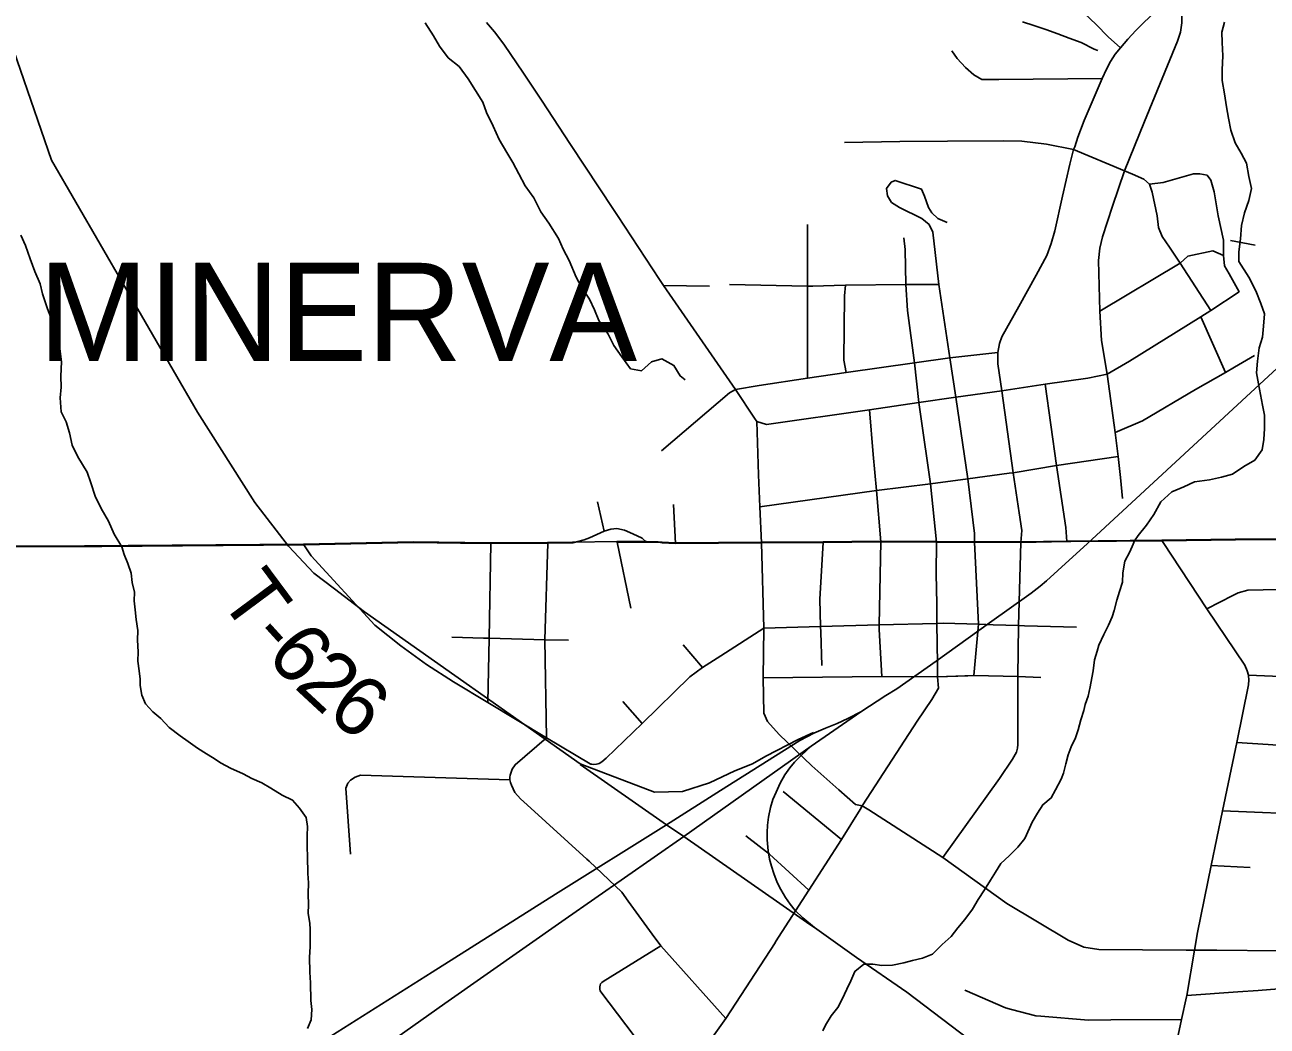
# Model space of a CAD drawing. Extents: x 0 to 34, y 0 to 22.
# Drawn here: x 4.481 to 5.679, y 16.545 to 17.511 of the extents above; entities that cross this region are included whole.
import ezdxf

# ---------------------------------------------------------------- set-up
doc = ezdxf.new("R2010")
doc.units = 0
for name, color, linetype in [('Default', 7, 'Continuous'), ('SH_Cut_Line', 7, 'Continuous'), ('SH_Data', 7, 'Continuous')]:
    doc.layers.add(name, color=color, linetype=linetype)

msp = doc.modelspace()

# ---------------------------------------------------------------- linework, layer by layer
at = {"layer": 'Default'}
for p, q in [((5.6519, 17.2539), (5.6423, 17.2712)), ((5.0967, 17.2599), (5.1412, 17.2591)), ((5.2408, 17.2592), (5.2612, 17.2598)), ((5.6388, 17.1759), (5.615, 17.2298)), ((5.6475, 17.181), (5.6667, 17.1924)), ((5.5396, 17.0545), (5.5375, 17.0747)), ((5.0396, 17.023), (5.033, 17.0511)), ((5.1082, 17.0111), (5.1063, 17.0485)), ((4.5548, 17.0081), (4.7497, 17.0097)), ((5.0652, 16.9486), (5.0519, 17.0123)), ((5.5778, 17.0136), (5.4898, 17.0128)), ((5.5789, 17.012), (5.5778, 17.0136)), ((5.1345, 16.8913), (5.1156, 16.9133)), ((5.3612, 16.8823), (5.3961, 16.8836)), ((5.3612, 16.8823), (5.3903, 16.8834)), ((5.3961, 16.8836), (5.4386, 16.8827)), ((5.4386, 16.8827), (5.4606, 16.8818)), ((5.076, 16.8373), (5.0576, 16.8587)), ((5.2684, 16.7254), (5.2122, 16.7717)), ((5.6252, 16.7002), (5.6628, 16.6984)), ((5.1077, 16.4842), (5.157, 16.5526))]:
    msp.add_line(p, q, dxfattribs=at)
for points in [[(4.7351, 17.0083), (4.7024, 17.0505), (4.6473, 17.1377), (4.5064, 17.3807), (4.4361, 17.5838), (4.404, 17.6885), (4.3215, 17.9209), (4.3028, 17.9921), (4.3143, 18.0833), (4.3281, 18.2195), (4.3343, 18.2932), (4.3327, 18.3689), (4.327, 18.4219)], [(5.5058, 17.0111), (5.7483, 17.2351), (5.9021, 17.375), (6.092, 17.5491), (6.2778, 17.7191)], [(5.3944, 17.5763), (5.4338, 17.5575), (5.4612, 17.546), (5.4969, 17.5281), (5.5142, 17.5118), (5.5257, 17.4999), (5.5375, 17.4893)], [(5.4934, 17.3938), (5.4965, 17.4031), (5.5026, 17.4191), (5.5133, 17.444), (5.5199, 17.4596), (5.524, 17.4686), (5.5279, 17.4759), (5.5324, 17.483), (5.5375, 17.4893), (5.5447, 17.4975), (5.5525, 17.506), (5.5932, 17.5464)], [(5.5314, 17.125), (5.5247, 17.1743), (5.5194, 17.2068), (5.5177, 17.235), (5.5163, 17.284), (5.5175, 17.296), (5.5203, 17.3069), (5.5299, 17.3364), (5.5414, 17.3705), (5.5608, 17.418), (5.5925, 17.4956), (5.5954, 17.5043), (5.5969, 17.5132), (5.5968, 17.5221), (5.5959, 17.532), (5.5932, 17.5464)], [(4.8669, 17.5133), (4.8747, 17.5009), (4.8805, 17.4907), (4.889, 17.4797), (4.8997, 17.4711), (4.9082, 17.4594), (4.9152, 17.4481), (4.9225, 17.4367), (4.9261, 17.4269), (4.9323, 17.4137), (4.9381, 17.4008), (4.9455, 17.3883), (4.9513, 17.3785), (4.9571, 17.3675), (4.9633, 17.3562), (4.9715, 17.3445), (4.9784, 17.3309), (4.9862, 17.3199), (4.9955, 17.3052), (4.9998, 17.295), (5.0056, 17.284), (5.0126, 17.2681), (5.0176, 17.2583), (5.0254, 17.2466), (5.0301, 17.2364), (5.0343, 17.2262), (5.0432, 17.213), (5.0487, 17.202), (5.0564, 17.1911), (5.0649, 17.1794), (5.0756, 17.1776), (5.0853, 17.1864), (5.0952, 17.1891), (5.1067, 17.1828), (5.1129, 17.1726), (5.1175, 17.1688)], [(4.9259, 17.5137), (4.9336, 17.5047), (4.9427, 17.4928), (4.9616, 17.4647), (4.9789, 17.4387), (5.0069, 17.396), (5.0484, 17.3332)], [(5.4432, 17.5142), (5.4539, 17.5108), (5.4657, 17.5068), (5.4771, 17.5027), (5.4882, 17.4986), (5.4996, 17.4942), (5.5123, 17.4878), (5.5157, 17.4867)], [(5.6378, 17.5141), (5.6352, 17.5042), (5.6357, 17.4943), (5.6363, 17.4814), (5.6356, 17.4681), (5.6358, 17.4578), (5.6378, 17.4449), (5.6398, 17.4324), (5.6419, 17.4214), (5.6439, 17.4097), (5.6482, 17.3975), (5.654, 17.3877), (5.6591, 17.3779), (5.6615, 17.365), (5.6639, 17.3536), (5.6614, 17.3418), (5.6573, 17.33), (5.6544, 17.3178), (5.6534, 17.3049), (5.6517, 17.2923), (5.6518, 17.2829), (5.6614, 17.2681), (5.668, 17.2549), (5.6731, 17.2424), (5.6766, 17.2326), (5.6756, 17.2208), (5.6746, 17.2101), (5.6713, 17.1998), (5.6699, 17.1869), (5.6689, 17.1755), (5.6706, 17.1649), (5.6746, 17.1444), (5.6766, 17.1349), (5.6764, 17.122), (5.6757, 17.1114), (5.6743, 17.1015), (5.6672, 17.0915), (5.6566, 17.0853), (5.6457, 17.078), (5.6351, 17.0749), (5.6233, 17.0725), (5.6089, 17.0705), (5.5987, 17.0658), (5.587, 17.0608), (5.5764, 17.0512), (5.5697, 17.0389), (5.5626, 17.0286), (5.5547, 17.0187), (5.5512, 17.0135)], [(5.375, 17.4864), (5.3799, 17.4788), (5.3879, 17.4703), (5.3961, 17.4631), (5.4037, 17.4588), (5.4159, 17.4587)], [(5.4159, 17.4587), (5.4203, 17.4587), (5.5199, 17.4596)], [(5.2712, 17.3978), (5.3246, 17.3988), (5.3706, 17.3992), (5.4249, 17.3996), (5.4424, 17.399), (5.4663, 17.3962), (5.4924, 17.391)], [(5.4231, 17.1584), (5.4194, 17.1842), (5.4192, 17.1951), (5.4207, 17.2041), (5.423, 17.2103), (5.4396, 17.2397), (5.4562, 17.2699), (5.4666, 17.2888), (5.4708, 17.3003), (5.4741, 17.3126), (5.4816, 17.3461), (5.4887, 17.3771), (5.4924, 17.391), (5.4934, 17.3938)], [(5.4924, 17.391), (5.5414, 17.3705), (5.5492, 17.3673), (5.5602, 17.3624), (5.5654, 17.3577), (5.5789, 17.3594), (5.6079, 17.3676), (5.614, 17.3677), (5.6212, 17.3664)], [(5.6423, 17.2712), (5.638, 17.279), (5.6371, 17.2888), (5.6368, 17.3035), (5.6317, 17.3272), (5.628, 17.3504), (5.6248, 17.3615), (5.6212, 17.3664)], [(5.3966, 17.0122), (5.3967, 17.0206), (5.3904, 17.0734), (5.3787, 17.1522), (5.3729, 17.19), (5.3623, 17.2609), (5.3564, 17.3115), (5.353, 17.3188), (5.3459, 17.3245), (5.3243, 17.3353), (5.3168, 17.34), (5.3127, 17.3464), (5.3118, 17.3535), (5.3164, 17.3597), (5.3202, 17.3613), (5.3457, 17.353), (5.3485, 17.346), (5.3523, 17.3353), (5.3557, 17.3299), (5.3613, 17.3245), (5.3704, 17.3206)], [(5.5654, 17.3577), (5.5681, 17.35), (5.573, 17.3272), (5.5741, 17.3158), (5.5777, 17.3072), (5.5849, 17.297), (5.5953, 17.2816), (5.6248, 17.2358)], [(5.0484, 17.3332), (5.0524, 17.3273), (5.0928, 17.2658)], [(5.2356, 17.1705), (5.2357, 17.2591), (5.2356, 17.3186)], [(4.4766, 17.3083), (4.4812, 17.2985), (4.4856, 17.2856), (4.4903, 17.2735), (4.4953, 17.2614), (4.4977, 17.2519), (4.5025, 17.2375), (4.5072, 17.2247), (4.5123, 17.2103), (4.5147, 17.1966), (4.5159, 17.1864), (4.5153, 17.1723), (4.5155, 17.1617), (4.5148, 17.1514), (4.5157, 17.1381)], [(5.3447, 17.1357), (5.3431, 17.147), (5.3387, 17.1852), (5.3321, 17.2357), (5.3306, 17.2609), (5.33, 17.2946), (5.3285, 17.3059)], [(5.5177, 17.235), (5.5953, 17.2816), (5.6024, 17.2881), (5.6268, 17.2935), (5.6371, 17.2888)], [(5.0928, 17.2658), (5.0967, 17.2599), (5.1661, 17.1595), (5.1845, 17.132)], [(5.1604, 17.261), (5.2357, 17.2591), (5.2408, 17.2592)], [(5.2612, 17.2598), (5.2724, 17.2601), (5.3306, 17.2609), (5.3623, 17.2609)], [(5.2728, 17.1759), (5.2708, 17.1879), (5.2713, 17.25), (5.2724, 17.2601)], [(5.4231, 17.1584), (5.4649, 17.1648), (5.506, 17.1704), (5.5247, 17.1743), (5.5462, 17.187), (5.615, 17.2298), (5.6248, 17.2358), (5.6519, 17.2539), (5.6519, 17.2539)], [(5.4231, 17.1584), (5.4649, 17.1648), (5.506, 17.1704), (5.5247, 17.1743), (5.5462, 17.187), (5.615, 17.2298), (5.6248, 17.2358), (5.6519, 17.2539), (5.6519, 17.2539)], [(5.0947, 17.1003), (5.1604, 17.1562), (5.1661, 17.1595), (5.1891, 17.1634), (5.2356, 17.1705), (5.2728, 17.1759), (5.3387, 17.1852), (5.3729, 17.19), (5.4192, 17.1951)], [(5.5323, 17.118), (5.5588, 17.1294), (5.61, 17.1594), (5.6388, 17.1759), (5.6475, 17.181)], [(5.4858, 17.0128), (5.4849, 17.0263), (5.476, 17.0863), (5.4649, 17.1648)], [(5.1845, 17.132), (5.1867, 17.1286), (5.1962, 17.1258), (5.2956, 17.1401), (5.3431, 17.147), (5.3787, 17.1522), (5.4231, 17.1584)], [(5.4414, 17.012), (5.4424, 17.0234), (5.4398, 17.0406), (5.4341, 17.0793), (5.4231, 17.1584)], [(4.5157, 17.1381), (4.5204, 17.1283), (4.5236, 17.1177), (4.5263, 17.1059), (4.5318, 17.0946), (4.5407, 17.0799), (4.5442, 17.0696), (4.5486, 17.0568), (4.5544, 17.0447), (4.5614, 17.0326), (4.5668, 17.0201), (4.5742, 17.0078)], [(5.3063, 17.0126), (5.3022, 17.0622), (5.2991, 17.097), (5.2956, 17.1401)], [(5.1914, 17.0116), (5.1897, 17.0462), (5.1884, 17.0771), (5.1867, 17.1286)], [(5.3601, 17.0124), (5.3543, 17.0685), (5.3447, 17.1357)], [(5.5375, 17.0747), (5.5353, 17.0949), (5.5323, 17.118), (5.5314, 17.125)], [(5.4302, 17.0788), (5.4341, 17.0793), (5.476, 17.0863), (5.5353, 17.0949)], [(5.1897, 17.0462), (5.3022, 17.0622), (5.3543, 17.0685), (5.3904, 17.0734), (5.4302, 17.0788)], [(4.9852, 17.0112), (5.0091, 17.0116), (5.0201, 17.0144), (5.0252, 17.0166), (5.0359, 17.0214), (5.0396, 17.023), (5.046, 17.0249), (5.0518, 17.0254), (5.059, 17.0238), (5.0672, 17.0204), (5.076, 17.016), (5.0804, 17.0122)], [(4.1345, 17.0111), (4.1998, 17.0105), (4.215, 17.011), (4.2236, 17.0113), (4.2347, 17.011), (4.2466, 17.0105), (4.2609, 17.0094), (4.2768, 17.0085), (4.3013, 17.0085), (4.3321, 17.0082), (4.4053, 17.008), (4.5384, 17.008), (4.5548, 17.0081)], [(4.4051, 17.0085), (4.5382, 17.0086), (4.7495, 17.0102), (4.8553, 17.0125), (4.9299, 17.0116), (4.9849, 17.0118), (5.0089, 17.0122), (5.0517, 17.0129), (5.0802, 17.0128), (5.0916, 17.0127), (5.0953, 17.0122), (5.1079, 17.0116), (5.1912, 17.0122), (5.2507, 17.0126), (5.3061, 17.0131), (5.3599, 17.0129), (5.3964, 17.0127), (5.4412, 17.0125), (5.4856, 17.0133), (5.5776, 17.0142), (5.6482, 17.0151), (5.706, 17.0155)], [(5.706, 17.0155), (5.6482, 17.0151), (5.5776, 17.0142), (5.4856, 17.0133), (5.4412, 17.0125), (5.3964, 17.0127), (5.3599, 17.0129), (5.3061, 17.0131), (5.2507, 17.0126), (5.1912, 17.0122), (5.1079, 17.0116), (5.0953, 17.0122), (5.0916, 17.0127), (5.0802, 17.0128), (5.0517, 17.0129), (5.0089, 17.0122), (4.9849, 17.0118), (4.9299, 17.0116), (4.8553, 17.0125), (4.7495, 17.0102), (4.5382, 17.0086), (4.4051, 17.0085)], [(4.5799, 16.9917), (4.5764, 17.0003), (4.5742, 17.0078)], [(5.0162, 16.7985), (4.8082, 16.9451), (4.7792, 16.9674), (4.7595, 16.9822), (4.7351, 17.0083)], [(4.7497, 17.0097), (4.8555, 17.0119), (4.9008, 17.0114)], [(4.7497, 17.0097), (4.7569, 16.999), (4.8181, 16.9321), (4.8432, 16.9124), (4.8682, 16.8941), (4.8942, 16.8774)], [(4.9008, 17.0114), (4.9301, 17.0111), (4.9852, 17.0112)], [(4.9273, 16.8575), (4.9287, 16.9197), (4.9301, 17.0111)], [(4.9838, 16.8236), (4.9822, 16.9182), (4.9852, 17.0112)], [(5.0519, 17.0123), (5.0804, 17.0122), (5.0918, 17.0122), (5.0955, 17.0116), (5.1082, 17.0111), (5.1914, 17.0116), (5.2509, 17.0121), (5.3063, 17.0126), (5.3601, 17.0124), (5.3966, 17.0122), (5.4414, 17.012)], [(5.6893, 16.6181), (5.6304, 16.6185), (5.609, 16.6187), (5.601, 16.6187), (5.5167, 16.6194), (5.5022, 16.6215), (5.487, 16.6282), (5.428, 16.6637), (5.3663, 16.708), (5.2947, 16.754), (5.2884, 16.7578), (5.2819, 16.7593), (5.2659, 16.7732), (5.2398, 16.7964), (5.2082, 16.8267), (5.1969, 16.8391), (5.1934, 16.8474), (5.1929, 16.8814), (5.1934, 16.9293), (5.1914, 17.0116)], [(5.2424, 16.6404), (5.2312, 16.6497), (5.2236, 16.657), (5.219, 16.663), (5.2145, 16.6693), (5.2099, 16.6771), (5.2063, 16.684), (5.203, 16.6925), (5.2008, 16.6996), (5.1991, 16.7065), (5.1978, 16.7144), (5.1968, 16.725), (5.1967, 16.7323), (5.1971, 16.7392), (5.1981, 16.7469), (5.2001, 16.7563), (5.2022, 16.7639), (5.2054, 16.7711), (5.2093, 16.7798), (5.2137, 16.7877), (5.2187, 16.7947), (5.2231, 16.8001), (5.2299, 16.8067), (5.2393, 16.8153), (5.287, 16.8487), (5.3113, 16.8642), (5.3219, 16.8709), (5.3597, 16.8976), (5.4113, 16.9344), (5.4513, 16.9631), (5.46, 16.9698), (5.4663, 16.975), (5.4772, 16.9848), (5.5058, 17.0111)], [(5.2494, 16.8933), (5.2484, 16.9253), (5.2483, 16.9308), (5.2475, 16.9572), (5.2509, 17.0121)], [(5.3073, 16.8827), (5.3049, 16.9279), (5.3048, 16.9324), (5.3063, 17.0126)], [(5.3612, 16.8823), (5.3609, 16.8948), (5.3605, 16.9339), (5.3603, 16.9528), (5.3599, 16.9818), (5.3601, 17.0124)], [(5.3961, 16.8836), (5.4007, 16.933), (5.3966, 17.0122)], [(5.4386, 16.8827), (5.4393, 16.9318), (5.4414, 17.012)], [(5.4898, 17.0128), (5.4858, 17.0128), (5.4414, 17.012)], [(5.4872, 16.8072), (5.4901, 16.8148), (5.4942, 16.8236), (5.4967, 16.8312), (5.4992, 16.8407), (5.5021, 16.8499), (5.5036, 16.8556), (5.5065, 16.8636), (5.5083, 16.8728), (5.51, 16.8815), (5.5111, 16.888), (5.5124, 16.8986), (5.515, 16.907), (5.5168, 16.9128), (5.5216, 16.9231), (5.526, 16.9322), (5.5297, 16.9403), (5.5315, 16.9464), (5.534, 16.9563), (5.5365, 16.9647), (5.5394, 16.9738), (5.5397, 16.9826), (5.5418, 16.994), (5.5466, 17.0028), (5.5499, 17.0104), (5.5512, 17.0135)], [(5.5778, 17.0136), (5.6484, 17.0145), (5.7062, 17.015), (5.7223, 17.0151), (5.7604, 17.0156), (5.8954, 17.0167)], [(5.5804, 16.4716), (5.5828, 16.4882), (5.5923, 16.5322), (5.5965, 16.5516), (5.6013, 16.5736), (5.6015, 16.575), (5.609, 16.6187), (5.612, 16.6357), (5.6252, 16.7002), (5.6361, 16.7532), (5.6497, 16.819), (5.6611, 16.8747), (5.6615, 16.8796), (5.6612, 16.8833), (5.661, 16.884), (5.6598, 16.8881), (5.6575, 16.8937), (5.6209, 16.9478), (5.5789, 17.012)], [(4.7532, 16.5431), (4.7568, 16.5515), (4.7574, 16.5614), (4.7566, 16.5701), (4.7563, 16.5872), (4.7554, 16.5974), (4.7552, 16.6118), (4.7558, 16.6217), (4.756, 16.6324), (4.7559, 16.6388), (4.7555, 16.6445), (4.7538, 16.6544), (4.7541, 16.6623), (4.7539, 16.673), (4.7541, 16.6836), (4.7536, 16.6927), (4.7534, 16.709), (4.7529, 16.7181), (4.7531, 16.7288), (4.7534, 16.7379), (4.7521, 16.7466), (4.7455, 16.7556), (4.7389, 16.7635), (4.729, 16.7683), (4.7179, 16.7749), (4.7091, 16.7801), (4.6995, 16.7842), (4.6911, 16.7886), (4.6789, 16.7941), (4.6701, 16.7989), (4.6616, 16.8045), (4.6559, 16.8079), (4.6471, 16.8134), (4.6382, 16.8201), (4.6306, 16.8253), (4.6198, 16.8335), (4.6117, 16.8422), (4.604, 16.8485), (4.5971, 16.8564), (4.5935, 16.8647), (4.5919, 16.8741), (4.5918, 16.8802), (4.5909, 16.8882), (4.5896, 16.8976), (4.5899, 16.9064), (4.5893, 16.9178), (4.5896, 16.9269), (4.5879, 16.9375), (4.587, 16.947), (4.5861, 16.9557), (4.5864, 16.964), (4.5843, 16.9735), (4.5831, 16.9822), (4.5799, 16.9917)], [(5.6209, 16.9478), (5.6459, 16.9609), (5.6512, 16.9633), (5.6603, 16.966), (5.7195, 16.9674), (5.8006, 16.9693), (5.833, 16.9701)], [(5.1934, 16.9293), (5.2483, 16.9308), (5.3048, 16.9324), (5.3605, 16.9339), (5.3665, 16.9341), (5.4007, 16.933), (5.4148, 16.9326), (5.4393, 16.9318), (5.4449, 16.9317), (5.4952, 16.9301)], [(5.0259, 16.7983), (5.0266, 16.7981), (5.0276, 16.798), (5.0291, 16.7979), (5.032, 16.798), (5.0334, 16.7983), (5.0347, 16.7988), (5.0371, 16.8003), (5.0415, 16.8038), (5.076, 16.8373), (5.122, 16.8822), (5.1345, 16.8913), (5.152, 16.9025), (5.1934, 16.9293)], [(4.8925, 16.9207), (4.9232, 16.9198), (4.9287, 16.9197), (4.9822, 16.9182), (5.0051, 16.9176)], [(5.0259, 16.7983), (4.9838, 16.8236), (4.9273, 16.8575), (4.8942, 16.8774)], [(5.1929, 16.8814), (5.3073, 16.8827), (5.3612, 16.8823)], [(5.2049, 16.6267), (5.2369, 16.6765), (5.2684, 16.7254), (5.2863, 16.7545), (5.2884, 16.7578), (5.2891, 16.7589), (5.3413, 16.8395), (5.3557, 16.8606), (5.3621, 16.8713), (5.3612, 16.8823)], [(5.3663, 16.708), (5.4207, 16.7843), (5.4334, 16.8029), (5.4371, 16.8097), (5.4382, 16.8134), (5.4386, 16.8169), (5.4386, 16.8179), (5.4386, 16.8229), (5.4386, 16.8827)], [(5.3903, 16.8834), (5.3961, 16.8836), (5.4386, 16.8827)], [(5.661, 16.884), (5.7232, 16.8815), (5.7739, 16.8776), (5.802, 16.8754)], [(4.7515, 16.5202), (4.8736, 16.5975), (4.9925, 16.6725), (5.0997, 16.7396), (5.1516, 16.7726), (5.2282, 16.8208), (5.2417, 16.8281), (5.253, 16.8327), (5.2643, 16.8373), (5.2746, 16.8422), (5.287, 16.8487)], [(5.0162, 16.7985), (5.0879, 16.7712), (5.1149, 16.7716), (5.1411, 16.78), (5.1655, 16.7918), (5.1825, 16.7985), (5.1955, 16.8058), (5.2265, 16.822), (5.2415, 16.8287)], [(4.1311, 16.0292), (4.2125, 16.0873), (4.3131, 16.1587), (4.4414, 16.2501), (4.5633, 16.3368), (4.7182, 16.4485), (4.8857, 16.5673), (5.0019, 16.6486), (5.1164, 16.7282), (5.2393, 16.8153)], [(5.157, 16.5526), (5.0942, 16.6228), (5.0859, 16.6341), (5.0627, 16.666), (5.0565, 16.6747), (5.025, 16.7044), (5.0229, 16.7063), (4.9651, 16.7589), (4.9589, 16.7647), (4.9534, 16.7709), (4.95, 16.7777), (4.9492, 16.7805), (4.9486, 16.7831), (4.9485, 16.7854), (4.9488, 16.7876), (4.9508, 16.7931), (4.9536, 16.7975), (4.9838, 16.8236)], [(5.6497, 16.819), (5.6801, 16.817), (5.7261, 16.814), (5.7309, 16.8137), (5.7817, 16.8103), (5.802, 16.809)], [(5.2503, 16.5407), (5.2529, 16.5464), (5.2584, 16.5552), (5.2648, 16.5633), (5.2692, 16.5713), (5.2736, 16.5809), (5.2773, 16.5889), (5.2814, 16.5981), (5.29, 16.605), (5.2987, 16.6052), (5.3075, 16.6038), (5.3177, 16.6043), (5.3287, 16.6063), (5.337, 16.6087), (5.3465, 16.6108), (5.3563, 16.6147), (5.3657, 16.624), (5.3743, 16.6317), (5.3806, 16.6401), (5.3873, 16.6482), (5.3948, 16.6582), (5.4004, 16.6674), (5.4063, 16.6769), (5.4122, 16.6861), (5.4171, 16.6938), (5.4223, 16.7022), (5.4301, 16.7095), (5.4384, 16.718), (5.4454, 16.7265), (5.4499, 16.7364), (5.4524, 16.7421), (5.4576, 16.7509), (5.4628, 16.759), (5.4707, 16.7655), (5.4748, 16.7732), (5.4803, 16.7835), (5.4825, 16.7893), (5.485, 16.7984), (5.4872, 16.8072)], [(5.2378, 16.6435), (5.2088, 16.6636), (5.1164, 16.7282), (5.0997, 16.7396), (5.0164, 16.7979)], [(4.7949, 16.7112), (4.7903, 16.7749), (4.7921, 16.7796), (4.7949, 16.7827), (4.7992, 16.7855), (4.8043, 16.7874), (4.9486, 16.7831)], [(5.6361, 16.7532), (5.7289, 16.7491), (5.733, 16.7489), (5.7815, 16.7468), (5.8009, 16.746)], [(5.2369, 16.6765), (5.1989, 16.7112), (5.1762, 16.7288)], [(5.5861, 16.3845), (5.5724, 16.3953), (5.5193, 16.4381), (5.4802, 16.4691), (5.4669, 16.4789), (5.4374, 16.4998), (5.4065, 16.5213), (5.3742, 16.5456), (5.3315, 16.5782), (5.283, 16.6114), (5.2424, 16.6404), (5.2378, 16.6435)], [(5.1077, 16.4842), (5.0362, 16.5783), (5.0356, 16.5795), (5.0353, 16.5809), (5.0353, 16.5831), (5.0355, 16.5848), (5.0361, 16.5861), (5.0366, 16.5867), (5.0372, 16.5874), (5.0384, 16.5883), (5.0942, 16.6228)], [(5.157, 16.5526), (5.2044, 16.6258), (5.2049, 16.6267)], [(5.3874, 16.58), (5.4268, 16.5629), (5.4324, 16.5614), (5.4558, 16.5552), (5.4606, 16.5549), (5.5068, 16.5512), (5.5282, 16.5513), (5.5965, 16.5516)], [(5.6015, 16.575), (5.6508, 16.5785), (5.6705, 16.5798), (5.6903, 16.5812)]]:
    msp.add_lwpolyline(points, dxfattribs=at)
at = {"layer": 'SH_Cut_Line'}
for points in [[(4.4051, 17.0085), (4.5382, 17.0086), (4.7495, 17.0102), (4.8553, 17.0125), (4.9299, 17.0116), (4.9849, 17.0118), (5.0089, 17.0122), (5.0517, 17.0129), (5.0802, 17.0128), (5.0916, 17.0127), (5.0953, 17.0122), (5.1079, 17.0116), (5.1912, 17.0122), (5.2507, 17.0126), (5.3061, 17.0131), (5.3599, 17.0129), (5.3964, 17.0127), (5.4412, 17.0125), (5.4856, 17.0133), (5.5776, 17.0142), (5.6482, 17.0151), (5.706, 17.0155)], [(5.706, 17.0155), (5.6482, 17.0151), (5.5776, 17.0142), (5.4856, 17.0133), (5.4412, 17.0125), (5.3964, 17.0127), (5.3599, 17.0129), (5.3061, 17.0131), (5.2507, 17.0126), (5.1912, 17.0122), (5.1079, 17.0116), (5.0953, 17.0122), (5.0916, 17.0127), (5.0802, 17.0128), (5.0517, 17.0129), (5.0089, 17.0122), (4.9849, 17.0118), (4.9299, 17.0116), (4.8553, 17.0125), (4.7495, 17.0102), (4.5382, 17.0086), (4.4051, 17.0085)]]:
    msp.add_lwpolyline(points, dxfattribs=at)
at = {"layer": 'SH_Data'}
msp.add_line((5.6438, 17.3033), (5.6675, 17.2989), dxfattribs=at)

# ---------------------------------------------------------------- texts
at = {"layer": 'Default'}
for s, height, rotation, p in [('MINERVA', 0.0947, 0, (4.494, 17.187)), ('MINERVA', 0.0947, 0, (4.4941, 17.187)), ('MINERVA', 0.0947, 0, (4.4943, 17.1871)), ('T', 0.0568, 306.6033, (4.6671, 16.9583)), ('-', 0.0568, 312.2852, (4.6964, 16.9194)), ('6', 0.0568, 312.3507, (4.7121, 16.9021)), ('2', 0.0568, 317.2061, (4.7394, 16.8725)), ('6', 0.0568, 323.2749, (4.7701, 16.8445))]:
    msp.add_text(s, height=height, rotation=rotation, dxfattribs=at).set_placement(p)

doc.saveas('drawing.dxf')
